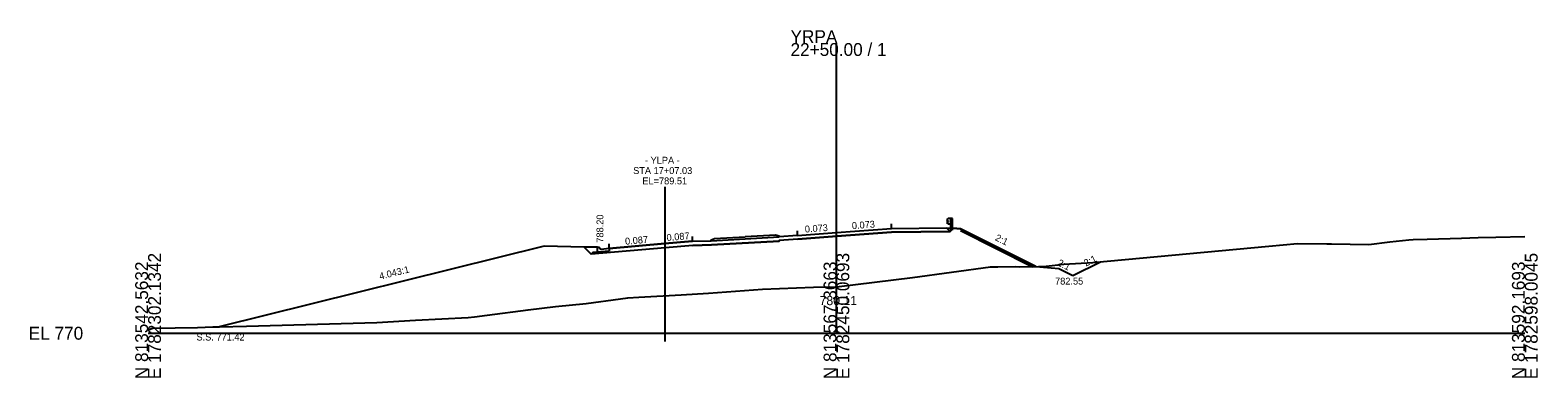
# Model space of a CAD drawing. Extents: x -26 to 2603, y -14 to 9545.
# Drawn here: x 974.3 to 1302.8, y 2490.3 to 2565.9 of the extents above; entities that cross this region are included whole.
import ezdxf

# ---------------------------------------------------------------- set-up
doc = ezdxf.new("R2010")
doc.units = 0
for name, color, linetype in [('Exist Cross Section Cell', 7, 'Continuous'), ('Exist XS Center Line Elevation Label', 7, 'Continuous'), ('Exist XS Ground Line', 7, 'Continuous'), ('Prop Conc 5in Monolithic Surface Mount Island', 7, 'Continuous'), ('Prop XS DDE', 7, 'Continuous'), ('Prop XS Ditch Standard Text', 7, 'Continuous'), ('Prop XS Dump Level', 7, 'Continuous'), ('Prop XS Earthwork Shape', 7, 'Continuous'), ('Prop XS EOT Tick Mark', 7, 'Continuous'), ('Prop XS Finish Grade', 7, 'Continuous'), ('Prop XS Finish Grade CurbGutter', 7, 'Continuous'), ('Prop XS Finish Grade Earthwork', 7, 'Continuous'), ('Prop XS Finish Grade Paved Shoulder', 7, 'Continuous'), ('Prop XS Finish Grade Pavement', 7, 'Continuous'), ('Prop XS Guardrail', 7, 'Continuous'), ('Prop XS Hydro Elevations', 7, 'Continuous'), ('Prop XS Hydro Fill Slope Data', 7, 'Continuous'), ('Prop XS Pvmt Edge Slope', 7, 'Continuous'), ('Prop XS SE Text', 7, 'Continuous'), ('Prop XS Side Slope Text', 7, 'Continuous'), ('Prop XS SS Elevation Text', 7, 'Continuous'), ('Prop XS Subgrade CurbGutter', 7, 'Continuous'), ('Prop XS Subgrade Earthwork', 7, 'Continuous'), ('Prop XS Vertical Lines Alignments', 7, 'Continuous')]:
    doc.layers.add(name, color=color, linetype=linetype)

msp = doc.modelspace()

# ---------------------------------------------------------------- linework, layer by layer
at = {"layer": 'Exist Cross Section Cell'}
for p, q in [((1150, 2500), (1150, 2563.13)), ((1000, 2500), (1150, 2500)), ((1150, 2500), (1300, 2500))]:
    msp.add_line(p, q, dxfattribs=at)
at = {"layer": 'Exist XS Ground Line'}
for p, q in [((1266.03, 2519.31), (1270.58, 2519.86)), ((1270.58, 2519.86), (1274.76, 2520.32)), ((1274.76, 2520.32), (1275.65, 2520.36)), ((1275.65, 2520.36), (1278.71, 2520.45)), ((1278.71, 2520.45), (1286.23, 2520.7)), ((1286.23, 2520.7), (1289.85, 2520.81)), ((1289.85, 2520.81), (1293.66, 2520.9)), ((1293.66, 2520.9), (1300, 2521.04)), ((1205.89, 2515.41), (1244.2, 2518.91)), ((1244.2, 2518.91), (1250.44, 2519.5)), ((1250.44, 2519.5), (1256.85, 2519.45)), ((1256.85, 2519.45), (1257.88, 2519.43)), ((1257.88, 2519.43), (1266.03, 2519.31)), ((1166.6, 2512.11), (1183.54, 2514.44)), ((1183.54, 2514.44), (1185.18, 2514.47)), ((1185.18, 2514.47), (1189, 2514.5)), ((1189, 2514.5), (1189.9, 2514.46)), ((1189.9, 2514.46), (1194.02, 2514.5)), ((1194.02, 2514.5), (1194.73, 2514.49)), ((1194.73, 2514.49), (1195.68, 2514.61)), ((1195.68, 2514.61), (1199.54, 2515.05)), ((1199.54, 2515.05), (1205.89, 2515.41)), ((1133.89, 2509.57), (1145, 2510.02)), ((1145, 2510.02), (1147.71, 2510.11)), ((1147.71, 2510.11), (1149.58, 2510.06)), ((1149.58, 2510.06), (1150, 2510.11)), ((1150, 2510.11), (1166.6, 2512.11)), ((1095.49, 2506.46), (1102.97, 2507.47)), ((1102.97, 2507.47), (1104.56, 2507.7)), ((1104.56, 2507.7), (1106.93, 2507.85)), ((1106.93, 2507.85), (1116.18, 2508.38)), ((1116.18, 2508.38), (1122.12, 2508.75)), ((1122.12, 2508.75), (1133.89, 2509.57)), ((1058.28, 2502.84), (1069.72, 2503.45)), ((1069.72, 2503.45), (1071.15, 2503.56)), ((1071.15, 2503.56), (1073.88, 2503.9)), ((1073.88, 2503.9), (1082.8, 2505.09)), ((1082.8, 2505.09), (1088.81, 2505.82)), ((1088.81, 2505.82), (1095.49, 2506.46)), ((1000, 2500.76), (1001.01, 2501.08)), ((1001.01, 2501.08), (1010.74, 2501.26)), ((1010.74, 2501.26), (1014.08, 2501.38)), ((1014.08, 2501.38), (1015.56, 2501.42)), ((1015.56, 2501.42), (1021.48, 2501.56)), ((1021.48, 2501.56), (1049.83, 2502.31)), ((1049.83, 2502.31), (1058.28, 2502.84))]:
    msp.add_line(p, q, dxfattribs=at)
at = {"layer": 'Prop Conc 5in Monolithic Surface Mount Island'}
for p, q in [((1122.71, 2520.31), (1123.45, 2520.58)), ((1122.71, 2520.14), (1122.71, 2520.31)), ((1123.45, 2520.58), (1130.1, 2521)), ((1136.74, 2521.37), (1130.1, 2521)), ((1137.5, 2521.14), (1136.74, 2521.37)), ((1137.5, 2520.98), (1137.5, 2521.14))]:
    msp.add_line(p, q, dxfattribs=at)
at = {"layer": 'Prop XS DDE'}
for p, q in [((1193.48, 2514.49), (1198.48, 2514.07)), ((1198.48, 2514.07), (1201.53, 2512.55)), ((1201.53, 2512.55), (1207.56, 2515.57))]:
    msp.add_line(p, q, dxfattribs=at)
at = {"layer": 'Prop XS Dump Level'}
for p, q in [((1118.67, 2520.03), (1112.61, 2519.51)), ((1141.5, 2521.27), (1150, 2521.89)), ((1150, 2521.89), (1162, 2522.77)), ((1112.61, 2519.51), (1100.49, 2518.45))]:
    msp.add_line(p, q, dxfattribs=at)
at = {"layer": 'Prop XS Earthwork Shape'}
msp.add_lwpolyline([(1086.34, 2518.94), (1015.5, 2501.42), (1015.56, 2501.42), (1021.48, 2501.56), (1049.83, 2502.31), (1058.28, 2502.84), (1069.72, 2503.45), (1071.15, 2503.56), (1073.88, 2503.9), (1082.8, 2505.09), (1088.81, 2505.82), (1095.49, 2506.46), (1102.97, 2507.47), (1104.56, 2507.7), (1106.93, 2507.85), (1116.18, 2508.38), (1122.12, 2508.75), (1133.89, 2509.57), (1145, 2510.02), (1147.71, 2510.11), (1149.58, 2510.06), (1150, 2510.11), (1166.6, 2512.11), (1183.54, 2514.44), (1185.18, 2514.47), (1189, 2514.5), (1189.9, 2514.46), (1193.48, 2514.49), (1177, 2522.73), (1175.47, 2522.84), (1174.78, 2522.15), (1162.03, 2521.98), (1150.06, 2521.1), (1141.56, 2520.48), (1137.5, 2520.18), (1137.5, 2520.06), (1122.75, 2519.22), (1118.72, 2519.12), (1112.69, 2518.6), (1096.59, 2517.2), (1095.01, 2518.76)], close=True, dxfattribs=at)
at = {"layer": 'Prop XS EOT Tick Mark'}
for p, q in [((1162, 2522.77), (1162, 2523.77)), ((1118.67, 2520.03), (1118.67, 2521.03)), ((1141.5, 2521.27), (1141.5, 2522.27)), ((1100.49, 2518.45), (1100.49, 2519.45))]:
    msp.add_line(p, q, dxfattribs=at)
at = {"layer": 'Prop XS Finish Grade'}
for p, q in [((1174, 2522.93), (1175.47, 2522.84)), ((1097.96, 2518.7), (1095.01, 2518.76))]:
    msp.add_line(p, q, dxfattribs=at)
at = {"layer": 'Prop XS Finish Grade CurbGutter'}
for p, q in [((1097.96, 2518.7), (1098.22, 2518.7)), ((1098.22, 2518.7), (1098.34, 2518.69)), ((1098.44, 2518.6), (1098.34, 2518.69)), ((1098.5, 2518.35), (1098.44, 2518.6)), ((1098.6, 2518.26), (1098.5, 2518.35)), ((1098.72, 2518.23), (1098.6, 2518.26)), ((1100.49, 2518.45), (1098.72, 2518.23))]:
    msp.add_line(p, q, dxfattribs=at)
at = {"layer": 'Prop XS Finish Grade Earthwork'}
for p, q in [((1175.47, 2522.84), (1177, 2522.73)), ((1177, 2522.73), (1193.48, 2514.49)), ((1086.34, 2518.94), (1015.5, 2501.42)), ((1095.01, 2518.76), (1086.34, 2518.94))]:
    msp.add_line(p, q, dxfattribs=at)
at = {"layer": 'Prop XS Finish Grade Paved Shoulder'}
for p, q in [((1118.67, 2520.03), (1122.71, 2520.14)), ((1122.71, 2520.14), (1137.5, 2520.98)), ((1141.5, 2521.27), (1137.5, 2520.98)), ((1162, 2522.77), (1174, 2522.93))]:
    msp.add_line(p, q, dxfattribs=at)
at = {"layer": 'Prop XS Finish Grade Pavement'}
for p, q in [((1112.61, 2519.51), (1118.67, 2520.03)), ((1141.5, 2521.27), (1150, 2521.89)), ((1150, 2521.89), (1162, 2522.77)), ((1100.49, 2518.45), (1112.61, 2519.51))]:
    msp.add_line(p, q, dxfattribs=at)
at = {"layer": 'Prop XS Guardrail'}
for p, q in [((1174.03, 2524.75), (1174, 2524.69)), ((1174, 2524.69), (1174.03, 2524.63)), ((1174.03, 2524.13), (1174, 2524.07)), ((1174, 2524.07), (1174.03, 2524.01)), ((1174.32, 2524.95), (1174.03, 2524.75)), ((1174.03, 2524.63), (1174.32, 2524.43)), ((1174.32, 2524.33), (1174.03, 2524.13)), ((1174.03, 2524.01), (1174.32, 2523.81)), ((1174.82, 2524.95), (1174.32, 2524.95)), ((1174.32, 2524.43), (1174.32, 2524.33)), ((1174.32, 2523.81), (1174.82, 2523.81)), ((1175.32, 2524.95), (1174.82, 2524.95)), ((1174.82, 2524.95), (1174.82, 2522.45)), ((1175.32, 2522.45), (1175.32, 2524.95))]:
    msp.add_line(p, q, dxfattribs=at)
at = {"layer": 'Prop XS Hydro Fill Slope Data'}
msp.add_line((1177, 2522.33), (1192.7, 2514.48), dxfattribs=at)
at = {"layer": 'Prop XS Pvmt Edge Slope'}
for p, q in [((1174, 2522.93), (1174.78, 2522.15)), ((1096.95, 2517.57), (1096.59, 2517.2)), ((1097.96, 2517.66), (1096.95, 2517.57))]:
    msp.add_line(p, q, dxfattribs=at)
at = {"layer": 'Prop XS Subgrade CurbGutter'}
for p, q in [((1097.96, 2517.66), (1097.96, 2518.7)), ((1100.49, 2517.87), (1097.96, 2517.66)), ((1100.49, 2518.45), (1100.49, 2517.87))]:
    msp.add_line(p, q, dxfattribs=at)
at = {"layer": 'Prop XS Subgrade Earthwork'}
for p, q in [((1122.75, 2519.22), (1137.5, 2520.06)), ((1141.56, 2520.48), (1137.5, 2520.18)), ((1137.5, 2520.06), (1137.5, 2520.18)), ((1141.56, 2520.48), (1150.06, 2521.1)), ((1150.06, 2521.1), (1162.03, 2521.98)), ((1162.03, 2521.98), (1174.78, 2522.15)), ((1174.78, 2522.15), (1175.47, 2522.84)), ((1096.59, 2517.2), (1095.01, 2518.76)), ((1112.69, 2518.6), (1096.59, 2517.2)), ((1118.72, 2519.12), (1112.69, 2518.6)), ((1118.72, 2519.12), (1122.75, 2519.22))]:
    msp.add_line(p, q, dxfattribs=at)
at = {"layer": 'Prop XS Vertical Lines Alignments'}
msp.add_line((1112.61, 2531.89), (1112.61, 2498.18), dxfattribs=at)

# ---------------------------------------------------------------- texts
at = {"layer": 'Exist Cross Section Cell'}
for s, p in [('YRPA', (1140, 2563.13)), ('22+50.00 / 1', (1140, 2560.33)), ('EL 770', (974, 2498.6))]:
    msp.add_text(s, height=2.8, dxfattribs=at).set_placement(p)
for s, p in [('E 1782302.1342', (1002.8, 2490)), ('E 1782450.0693', (1152.8, 2490)), ('E 1782598.0045', (1302.8, 2490)), ('N 813542.5632', (1000, 2490)), ('N 813567.3663', (1150, 2490)), ('N 813592.1693', (1300, 2490))]:
    msp.add_text(s, height=2.8, rotation=90, dxfattribs=at).set_placement(p)
at = {"layer": 'Exist XS Center Line Elevation Label'}
msp.add_text('780.11', height=2, dxfattribs=at).set_placement((1146.32, 2506.11))
at = {"layer": 'Prop XS Ditch Standard Text'}
msp.add_text('782.55', height=1.5, dxfattribs=at).set_placement((1197.64, 2510.59))
at = {"layer": 'Prop XS Dump Level'}
msp.add_text('Case4', height=0.04, dxfattribs=at).set_placement((1174, 2522.49))
at = {"layer": 'Prop XS Hydro Elevations'}
msp.add_text('788.20', height=1.5, rotation=90, dxfattribs=at).set_placement((1099.22, 2519.7))
at = {"layer": 'Prop XS SE Text'}
for s, rotation, p in [('0.073', 4.1928, (1143.17, 2521.89)), ('0.073', 4.1928, (1153.42, 2522.64)), ('0.087', 4.9765, (1104, 2519.25)), ('0.087', 4.9458, (1113.05, 2520.05))]:
    msp.add_text(s, height=1.5, rotation=rotation, dxfattribs=at).set_placement(p)
at = {"layer": 'Prop XS Side Slope Text'}
for s, rotation, p in [('2:1', 333.4349, (1184.44, 2520.29)), ('2:1', 26.5651, (1204.37, 2514.48)), ('4.043:1', 13.8913, (1050.56, 2511.64)), ('2:1', 333.4349, (1198.01, 2514.85))]:
    msp.add_text(s, height=1.5, rotation=rotation, dxfattribs=at).set_placement(p)
at = {"layer": 'Prop XS SS Elevation Text'}
msp.add_text('S.S. 771.42', height=1.5, dxfattribs=at).set_placement((1010.55, 2498.42))
at = {"layer": 'Prop XS Vertical Lines Alignments'}
for s, p in [('- YLPA -', (1108.28, 2536.89)), ('STA 17+07.03', (1105.7, 2534.64)), ('EL=789.51', (1107.71, 2532.39))]:
    msp.add_text(s, height=1.5, dxfattribs=at).set_placement(p)

doc.saveas('drawing.dxf')
